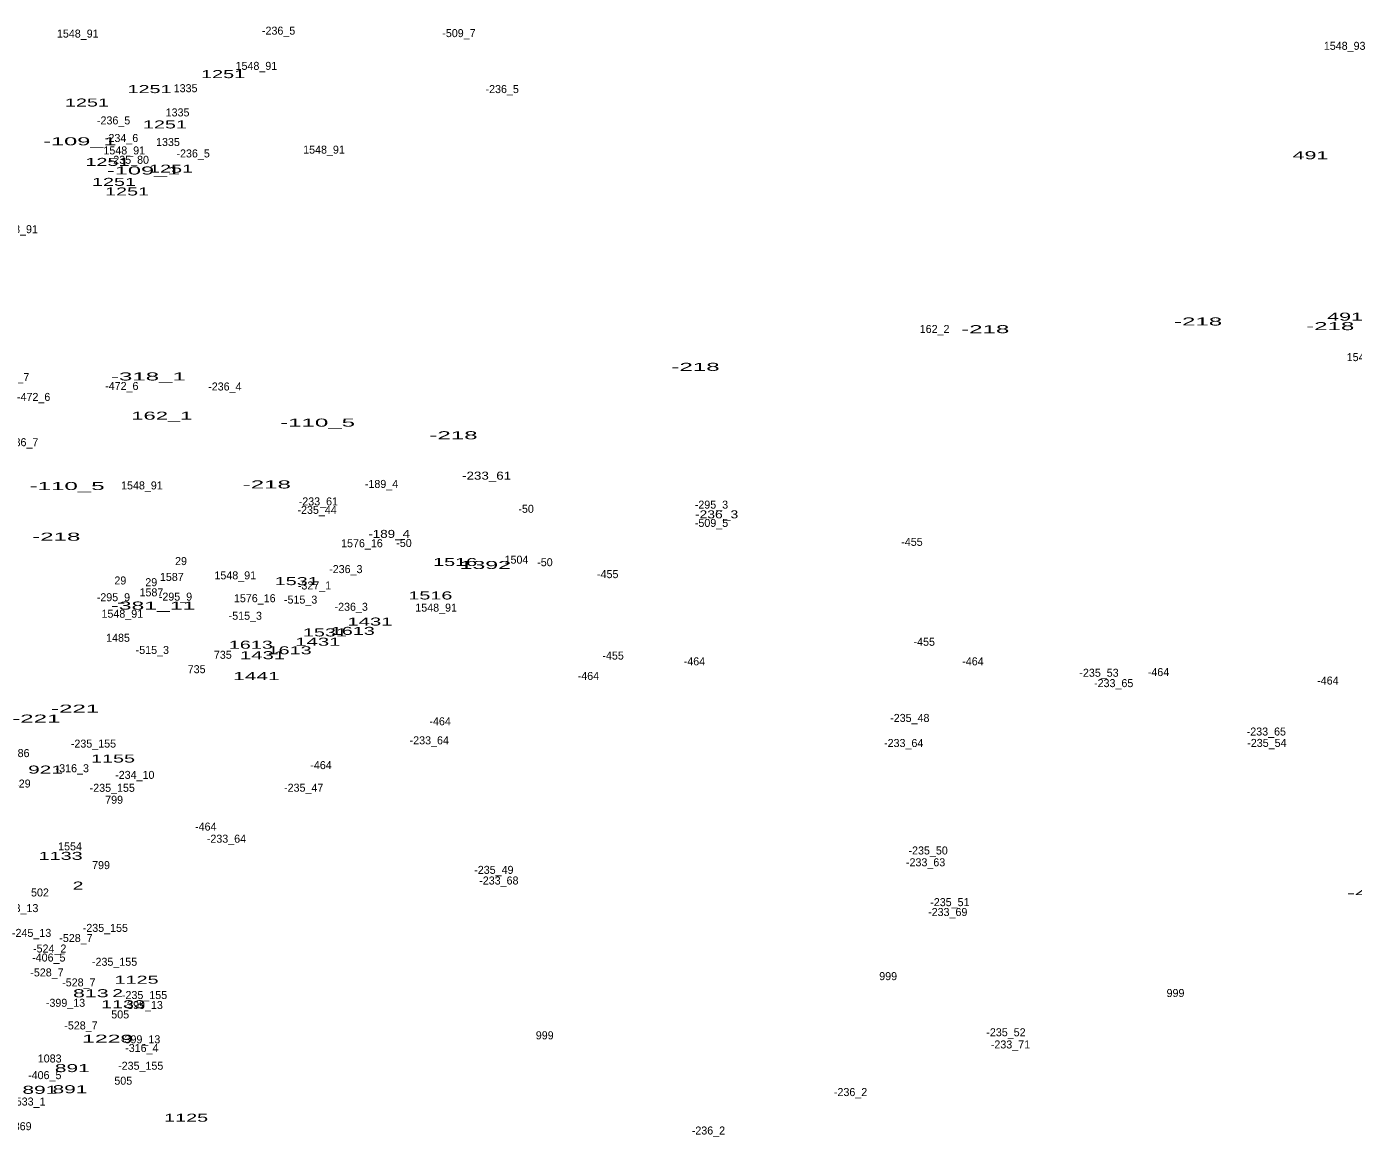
# Model space of a CAD drawing. Extents: x -660434 to -656144, y -997850 to -994016.
# Drawn here: x -658353 to -657690, y -996086 to -995533 of the extents above; entities that cross this region are included whole.
import ezdxf
from ezdxf.enums import TextEntityAlignment as Align

# ---------------------------------------------------------------- set-up
doc = ezdxf.new("R2010")
doc.units = 0
doc.header["$LTSCALE"] = 1.6
doc.layers.add('24', color=7, linetype='Continuous')

msp = doc.modelspace()

# ---------------------------------------------------------------- texts
at = {"layer": '24'}
for s, p in [('1548_91', (-658327.441, -995538.32)), ('-236_5', (-658227.058, -995536.86)), ('-509_7', (-658136.927, -995538.09)), ('1548_93', (-657694.227, -995544.44)), ('1548_91', (-658238.161, -995554.46)), ('1335', (-658273.54, -995565.62)), ('-236_5', (-658115.308, -995566.06)), ('1335', (-658277.57, -995577.72)), ('-236_5', (-658309.528, -995581.71)), ('-234_6', (-658305.552, -995590.52)), ('1335', (-658282.37, -995592.51)), ('1548_91', (-658304.211, -995596.72)), ('-236_5', (-658269.778, -995598.23)), ('1548_91', (-658204.371, -995596.33)), ('-235_80', (-658301.655, -995601.4)), ('1548_91', (-658357.781, -995636.09)), ('162_2', (-657899.184, -995685.95)), ('1548_93', (-657682.787, -995700.02)), ('-486_7', (-658359.988, -995710.01)), ('-472_6', (-658349.498, -995719.92)), ('-472_6', (-658305.428, -995714.45)), ('-236_4', (-658253.932, -995714.71)), ('-486_7', (-658355.468, -995742.56)), ('1548_91', (-658295.381, -995764.15)), ('-189_4', (-658175.626, -995763.41)), ('-233_61', (-658207.191, -995772.14)), ('-235_44', (-658207.81, -995776.37)), ('-50', (-658103.349, -995775.84)), ('-295_3', (-658010.728, -995773.76)), ('-509_5', (-658010.692, -995782.9)), ('1576_16', (-658185.407, -995793.05)), ('-50', (-658164.399, -995792.93)), ('-455', (-657910.499, -995792.36)), ('29', (-658275.833, -995801.96)), ('-236_3', (-658193.458, -995805.98)), ('1504', (-658108.178, -995801.25)), ('-50', (-658093.939, -995802.54)), ('29', (-658306.163, -995811.66)), ('29', (-658290.713, -995812.52)), ('1587', (-658280.436, -995809.9)), ('1548_91', (-658248.721, -995809.1)), ('-455', (-658062.569, -995808.49)), ('1587', (-658290.616, -995817.59)), ('-295_9', (-658278.613, -995819.74)), ('-327_1', (-658209.132, -995814.16)), ('-295_9', (-658309.623, -995820.03)), ('1576_16', (-658238.977, -995820.52)), ('-515_3', (-658216.056, -995821.23)), ('-236_3', (-658190.778, -995824.81)), ('1548_91', (-658148.321, -995825.24)), ('1548_91', (-658305.171, -995828.27)), ('-515_3', (-658243.706, -995829.3)), ('1485', (-658307.324, -995840.3)), ('-455', (-657904.359, -995842.3)), ('-515_3', (-658290.176, -995846.39)), ('735', (-658254.953, -995848.8)), ('-455', (-658059.879, -995849.21)), ('-464', (-658019.229, -995852.08)), ('-464', (-657880.019, -995852.07)), ('735', (-658268.013, -995856)), ('-464', (-658072.219, -995859.38)), ('-235_53', (-657817.021, -995857.78)), ('-464', (-657787.279, -995857.45)), ('-233_65', (-657809.677, -995862.96)), ('-464', (-657702.619, -995861.68)), ('-464', (-658146.339, -995882.04)), ('-235_48', (-657911.576, -995880.36)), ('-233_64', (-658151.751, -995891.56)), ('-233_65', (-657733.377, -995887.16)), ('586', (-658356.013, -995897.94)), ('-235_155', (-658319.605, -995893.2)), ('-233_64', (-657914.631, -995892.91)), ('-235_54', (-657733.106, -995892.85)), ('-316_3', (-658330.182, -995905.51)), ('-464', (-658205.859, -995903.94)), ('-234_10', (-658298.933, -995908.83)), ('1429', (-658356.95, -995913.16)), ('-235_155', (-658310.195, -995915.29)), ('-235_47', (-658214.521, -995915.24)), ('799', (-658309.273, -995921.26)), ('-464', (-658263.459, -995934.67)), ('1554', (-658331.304, -995944.54)), ('-233_64', (-658253.131, -995940.73)), ('-235_50', (-657902.415, -995946.61)), ('799', (-658315.803, -995953.93)), ('-235_49', (-658119.471, -995956.3)), ('-233_63', (-657903.687, -995952.51)), ('-233_68', (-658116.977, -995961.62)), ('502', (-658346.331, -995967.6)), ('-553_13', (-658356.945, -995975.41)), ('-233_69', (-657892.622, -995977.38)), ('-235_51', (-657891.555, -995972.44)), ('-235_155', (-658313.655, -995985.3)), ('-245_13', (-658350.509, -995987.8)), ('-528_7', (-658328.348, -995990.36)), ('-524_2', (-658341.467, -995995.61)), ('-406_5', (-658341.926, -996000.12)), ('-235_155', (-658309.045, -996002.24)), ('-528_7', (-658342.838, -996007.55)), ('999', (-657922.403, -996009.41)), ('-528_7', (-658326.908, -996012.54)), ('999', (-657778.783, -996017.86)), ('-399_13', (-658333.566, -996022.74)), ('-235_155', (-658294.065, -996018.87)), ('-399_13', (-658294.726, -996023.85)), ('505', (-658306.231, -996028.55)), ('-528_7', (-658325.848, -996034.05)), ('-235_52', (-657863.521, -996037.47)), ('-399_13', (-658296.026, -996040.99)), ('999', (-658094.053, -996038.99)), ('-233_71', (-657861.271, -996043.56)), ('1083', (-658341.484, -996050.58)), ('-316_4', (-658295.426, -996045.35)), ('-235_155', (-658295.985, -996054.2)), ('-406_5', (-658343.936, -996058.9)), ('505', (-658304.691, -996061.68)), ('-236_2', (-657941.188, -996067.36)), ('-533_1', (-658351.896, -996072.09)), ('369', (-658354.988, -996084.42)), ('-236_2', (-658012.228, -996086.57))]:
    msp.add_text(s, height=4, dxfattribs=at).set_placement(p, align=Align.CENTER)
for s, width, p in [('1251', 1.85, (-658254.794, -995558.57)), ('1251', 1.85, (-658291.564, -995566.06)), ('1251', 1.85, (-658322.854, -995572.78)), ('1251', 1.85, (-658283.874, -995583.73)), ('-109_1', 2.2, (-658326.409, -995592.15)), ('491', 2, (-657711.328, -995599.13)), ('1251', 1.85, (-658312.584, -995602.46)), ('-109_1', 2.2, (-658294.529, -995606.75)), ('1251', 1.85, (-658280.804, -995605.82)), ('1251', 1.85, (-658309.324, -995612.44)), ('1251', 1.85, (-658302.794, -995617.23)), ('491', 2, (-657694.048, -995679.8)), ('-218', 2.25, (-657873.871, -995686.06)), ('-218', 2.25, (-657767.501, -995682.22)), ('-218', 2.25, (-657701.451, -995684.53)), ('-218', 2.25, (-658018.681, -995704.89)), ('-318_1', 2.25, (-658292.137, -995709.69)), ('162_1', 2.05, (-658285.42, -995729.3)), ('-110_5', 2.25, (-658207.574, -995732.76)), ('-218', 2.25, (-658139.651, -995739.08)), ('-233_61', 1.25, (-658123.101, -995759.27)), ('-110_5', 2.25, (-658332.764, -995764.46)), ('-218', 2.25, (-658232.961, -995763.66)), ('-236_3', 1.3, (-658008.17, -995778.61)), ('-218', 2.25, (-658338.181, -995789.78)), ('-189_4', 1.25, (-658171.81, -995788.38)), ('1516', 1.85, (-658138.819, -995802.44)), ('1392', 2.15, (-658123.763, -995803.92)), ('1531', 1.85, (-658218.014, -995811.98)), ('1516', 1.85, (-658151.209, -995819.15)), ('-381_11', 2.15, (-658289.714, -995824.21)), ('1431', 1.9, (-658181.419, -995832.19)), ('1531', 1.85, (-658203.904, -995837.62)), ('1613', 1.85, (-658189.969, -995836.85)), ('1613', 1.85, (-658240.939, -995843.77)), ('1431', 1.9, (-658207.439, -995842.27)), ('1431', 1.9, (-658235.089, -995849)), ('1613', 1.85, (-658221.559, -995846.55)), ('1441', 1.95, (-658238.155, -995859.44)), ('-221', 2.25, (-658328.751, -995875.71)), ('-221', 2.25, (-658348.151, -995880.7)), ('1155', 1.85, (-658309.804, -995900.67)), ('921', 1.95, (-658343.563, -995906.18)), ('1133', 1.85, (-658336.004, -995949.3)), ('2', 1.8, (-658327.301, -995964.14)), ('-401', 2.25, (-657681.022, -995967.85)), ('1125', 1.85, (-658298.044, -996011.21)), ('813', 2, (-658320.917, -996017.96)), ('2', 1.8, (-658307.531, -996017.92)), ('1133', 1.85, (-658304.804, -996023.45)), ('1229', 2.15, (-658312.493, -996040.68)), ('891', 1.95, (-658330.173, -996055.38)), ('891', 1.95, (-658346.393, -996066.23)), ('891', 1.95, (-658331.323, -996065.94)), ('1125', 1.85, (-658273.284, -996080.17))]:
    msp.add_text(s, height=4, dxfattribs=dict(at, width=width)).set_placement(p, align=Align.CENTER)

doc.saveas('drawing.dxf')
